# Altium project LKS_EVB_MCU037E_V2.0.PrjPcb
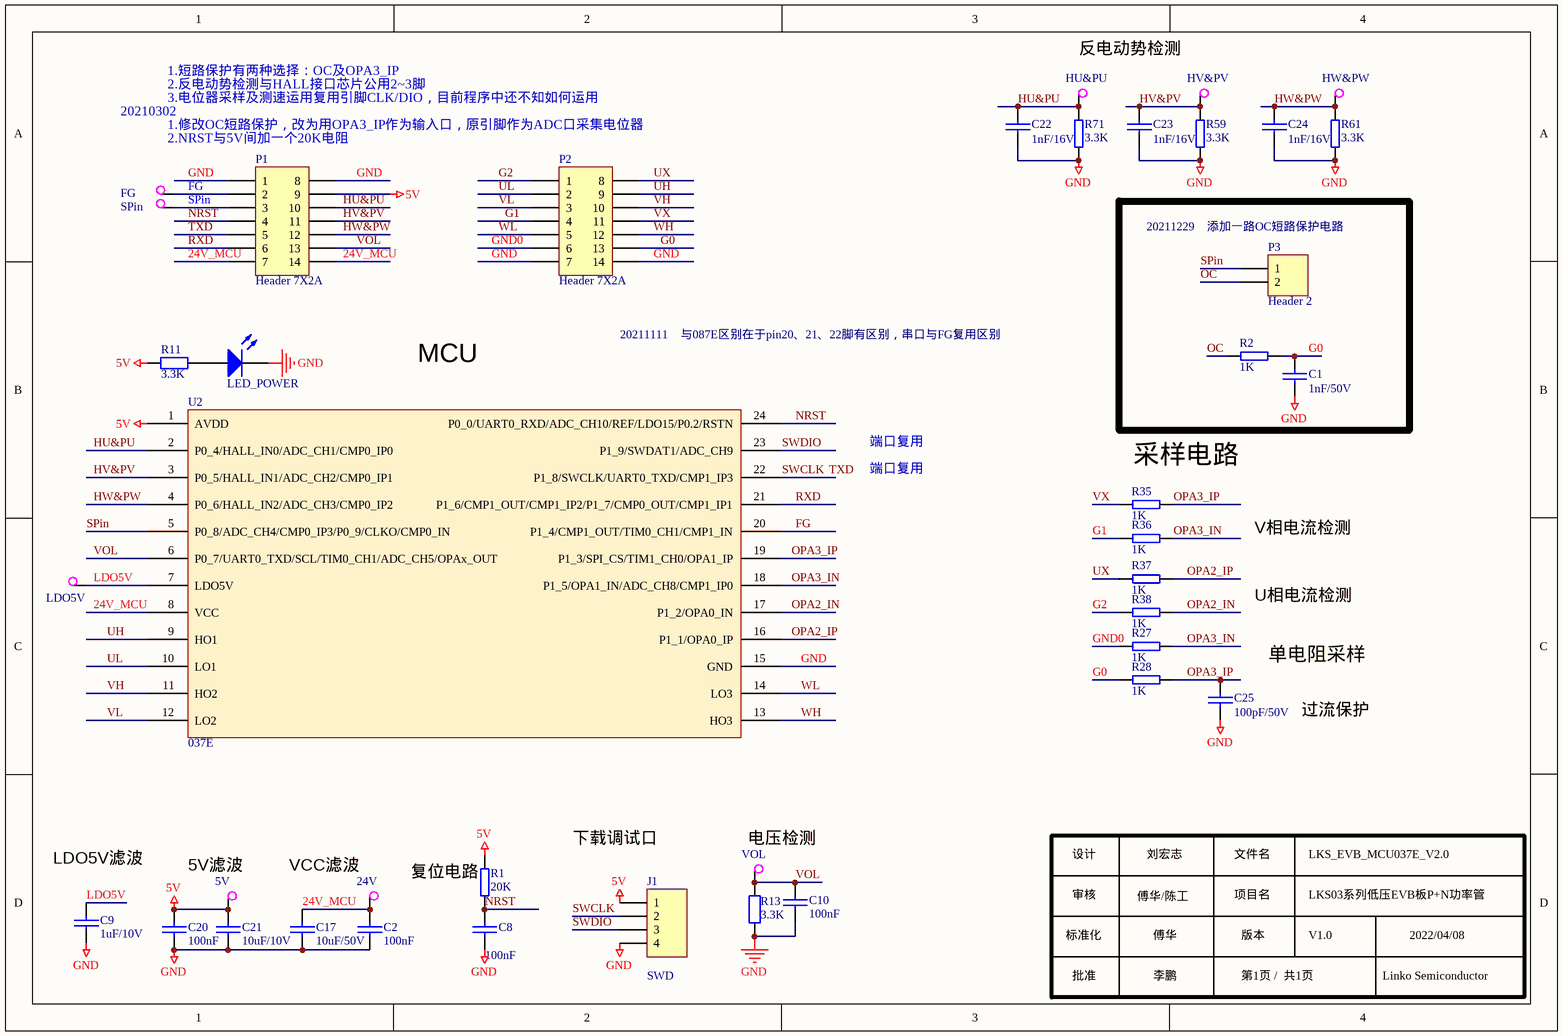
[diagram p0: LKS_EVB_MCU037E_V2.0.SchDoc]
1 sheet, 40 parts. Net scope: global (net labels, ports and power ports of the same name join across sheets).
Board file: LKS_EVB_MCU037E_V2.0.PcbDoc

## Sheet LKS_EVB_MCU037E_V2.0.SchDoc: LKS087_DEMO_V2.0_200109
size A4; Revision: V1.0; SheetNumber: 1; SheetTotal: 1

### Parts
5V  TestP  [TP-40]  (value not drawn)
24V  TestP  [TP-40]  (value not drawn)
C1  1nF/50V  [0805C]
C2  100nF  [0805C]
C8  100nF  [0805C]
C9  1uF/10V  [0805C]
C10  100nF  [0805C]
C17  10uF/50V  [1206]
C20  100nF  [0805C]
C21  10uF/10V  [0805C]
C22  1nF/16V  [0805C]
C23  1nF/16V  [0805C]
C24  1nF/16V  [0805C]
C25  100pF/50V  [0805C]
FG  TestP  [TP-40]  (value not drawn)
HU&PU  TestP  [TP-40]  (value not drawn)
HV&PV  TestP  [TP-40]  (value not drawn)
HW&PW  TestP  [TP-40]  (value not drawn)
J1  SWD  [SIP4-2.5]
LDO5V  TestP  [TP-40]  (value not drawn)
LED_POWER  (no value)  [0805D]
P1  Header 7X2A  [HDR2X7_CEN]
P2  Header 7X2A  [HDR2X7_CEN]
P3  Header 2  [HDR1X2]
R1  20K  [0805R]
R2  1K  [0805R]
R11  3.3K  [0603R]
R13  3.3K  [0805R]
R27  1K  [0805R]
R28  1K  [0805R]
R35  1K  [0805R]
R36  1K  [0805R]
R37  1K  [0805R]
R38  1K  [0805R]
R59  3.3K  [0805R]
R61  3.3K  [0805R]
R71  3.3K  [0805R]
SPin  TestP  [TP-40]  (value not drawn)
U2  037E  [SSOP24]
VOL  TestP  [TP-40]  (value not drawn)

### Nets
5V: 5V.1 C20.1 C21.1 J1.1 P1.9 R1.1 R11.2 U2.1(AVDD)
GND: C1.1 C2.2 C8.2 C9.2 C10.2 C17.1 C20.2 C21.2 C22.1 C23.1 C24.1 C25.1 J1.4 LED_POWER.2(K) P1.1 P1.8 P2.7 P2.14 R13.2 R59.1 R61.1 R71.1 U2.15(GND)
24V_MCU: 24V.1 C2.1 C17.2 P1.7 P1.14 U2.8(VCC)
FG: FG.1 P1.2 U2.20(P1_4/CMP1_OUT/TIM0_CH1/CMP1_IN)
G0: C1.2 P2.13 R2.1 R28.2
G1: P2.4 R36.1
G2: P2.1 R38.1
GND0: P2.6 R27.2
HU&PU: C22.2 HU&PU.1 P1.10 R71.2 U2.2(P0_4/HALL_IN0/ADC_CH1/CMP0_IP0)
HV&PV: C23.2 HV&PV.1 P1.11 R59.2 U2.3(P0_5/HALL_IN1/ADC_CH2/CMP0_IP1)
HW&PW: C24.2 HW&PW.1 P1.12 R61.2 U2.4(P0_6/HALL_IN2/ADC_CH3/CMP0_IP2)
LDO5V: C9.1 LDO5V.1 U2.7(LDO5V)
NRST: C8.1 P1.4 R1.2 U2.24(P0_0/UART0_RXD/ADC_CH10/REF/LDO15/P0.2/RSTN)
OC: P3.2 R2.2
OPA2_IN: R38.2 U2.17(P1_2/OPA0_IN)
OPA2_IP: R37.2 U2.16(P1_1/OPA0_IP)
OPA3_IN: R27.1 R36.2 U2.18(P1_5/OPA1_IN/ADC_CH8/CMP1_IP0)
OPA3_IP: C25.2 R28.1 R35.2 U2.19(P1_3/SPI_CS/TIM1_CH0/OPA1_IP)
RXD: P1.6 U2.21(P1_6/CMP1_OUT/CMP1_IP2/P1_7/CMP0_OUT/CMP1_IP1)
SPin: P1.3 P3.1 SPin.1 U2.5(P0_8/ADC_CH4/CMP0_IP3/P0_9/CLKO/CMP0_IN)
SWCLK: J1.2 P1.5 U2.22(P1_8/SWCLK/UART0_TXD/CMP1_IP3)  [also labelled TXD]
SWDIO: J1.3 U2.23(P1_9/SWDAT1/ADC_CH9)
UH: P2.9 U2.9(HO1)
UL: P2.2 U2.10(LO1)
UX: P2.8 R37.1
VH: P2.10 U2.11(HO2)
VL: P2.3 U2.12(LO2)
VOL: C10.1 P1.13 R13.1 U2.6(P0_7/UART0_TXD/SCL/TIM0_CH1/ADC_CH5/OPAx_OUT) VOL.1
VX: P2.11 R35.1
WH: P2.12 U2.13(HO3)
WL: P2.5 U2.14(LO3)
NetLED_POWER_1: LED_POWER.1(A) R11.1

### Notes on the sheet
- 20210302
- 1.短路保护有两种选择：OC及OPA3_IP
- 2.反电动势检测与HALL接口芯片公用2~3脚
- 3.电位器采样及测速运用复用引脚CLK/DIO，目前程序中还不知如何运用
- 1.修改OC短路保护，改为用OPA3_IP作为输入口，原引脚作为ADC口采集电位器
- 2.NRST与5V间加一个20K电阻
- 20211229
- (near P3) 添加一路OC短路保护电路
- MCU
- 20211111
- 与087E区别在于pin20、21、22脚有区别，串口与FG复用区别
- 端口复用
- (near R35) 采样电路
- V相电流检测
- U相电流检测
- 过流保护
- (near C9) LDO5V滤波
- (near 5V) 5V滤波
- VCC滤波
- 复位电路
- 设计
- 审核
- 傅华/陈工
- 刘宏志
- 文件名
- 项目名
- LKS_EVB_MCU037E_V2.0
- LKS03系列低压EVB板P+N功率管
- 标准化
- 批准
- 傅华
- 李鹏
- 版本
- 第1页 /  共1页
- V1.0
- Linko Semiconductor
- 2022/04/08
- Labels drawn without touching a wire or pin: 下载调试口, 单电阻采样, 反电动势检测, 电压检测

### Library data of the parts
C1 C8 C9 C20-C25 = C: Capacitor
C2 C10 C17 = CAP: Capacitor
J1 = Header 4: Header, 4-Pin
LED_POWER = LED2: Typical RED, GREEN, YELLOW, AMBER GaAs LED
P1 P2 = Header 7X2A: Header, 7-Pin, Dual row
P3 = Header 2: Header, 2-Pin
R1 R2 R27 R28 R35-R38 = RES2-1
R11 R13 = Res2: Resistor
R59 R61 R71 = RES/1
U2 = LKS32MC037EM6S8: chip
